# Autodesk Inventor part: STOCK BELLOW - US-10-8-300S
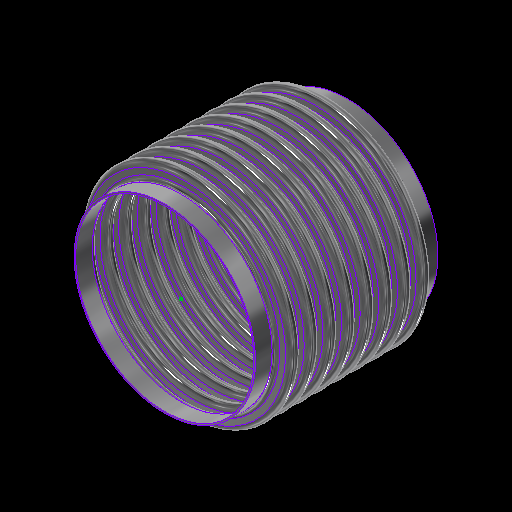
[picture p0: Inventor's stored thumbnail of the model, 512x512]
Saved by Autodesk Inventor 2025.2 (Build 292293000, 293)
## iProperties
Category: 18 GA (0.048 THICK)
RuleStatus: InUse
Created: 2024-01
Part Number: STOCK BELLOW - US-10-8-300S
Project: =STOCK BELLOWS: <Stock Number><SFILL>
Material: ASTM A240-304
Description: =STOCK BELLOWS: <Stock Number>, <SID_> I.D., <SOD_> O.D., <SPLY_> PLY, <Category>, <SNET_CONS> CONS.<PITCH_><STANGENT_> TANGENT<SFILL>
Document SubType Name: Sheet Metal
Designer: GS
Stock Number: U.S-10-8-300S
Surface Area: 10342.1 cm^2
Volume: 1245.47 cm^3
Sheet Metal Rule: Default
Appearance: STAINLESS STEEL
Mass: 10035.1 g
Density: 8.05729 g/cm^3
THK: 0.036
ID: 3.500
OD: 4.250
CONS_: 2
PITCH: 0.500
TANGENT: 0.500
BELLOWS_UPSET: 0.000
d79: 1.000
d82: 1.000
d83: 26.000
d84: 24.000
d174: 8
d214: 8
STHK_: 0.048
SID_: 10.750
SOD_: 12.750
SPITCH_: 1.125
STANGENT__: 1.000
SBELLOWS_UPSET_: 0.000
SDIFF_TAN: 1.000
d252: 2
d275: 2
d287: 0.050
d289: 0.500
d290: 0.000
SOD_NECK: 10 15/16
PLY: 1
PSET: 4.178
PBAR: 1.035
COUNTER: 1.500
NET_TUBE: 3.071
CONS: 2
S_CONS: 0
NET_CONS: 2
ID_M: 88.90 mm
OD_M: 107.95 mm
THK_M: 0.91 mm
ID_U: 3.500 in
OD_U: 4.250 in
THK_U: 0.036 in
TANGENT2: 0.500
TAN_TO_TAN: 1.000 in
d80: 2.571
d81: 10
SID: 2.375
SCONS_: 8
SPITCH: 0.250
STANGENT_: 1.000
SBELLOWS_UPSET: 0.000
SNET_CONS: 8
SS_CONS: 0
SCONS: 8
d190: 8
d191: 1
d192: 1
d193: 8
d194: 0
SIZE: 10.00
PRESSURE: 300
d230: 8
STANGENT: 4.000
SPLY_: 2
d233: 8
d234: 0
d263: 2
d265: 1
d268: 2
d269: 0
d286: 2
d288: 1
d291: 2
d292: 0
SREROLL: 0.750
BLETP: 0.000 ul
PRES_Copy: 85
MATTABLE: 20 GA (0.036 THICK)
PART_NUMBER: U.S-10-8-300S
PITCH_: =, <SPITCH_> PITCH,
CFILL: .
SFILL: .
MESH: ,
COMP: 1.52
EXT: 0.76
LAT: 0.38
ANG: 573
ASR: 6274
LSR: 20302
ANSR: 1890
PRES: 300
COMPM: 15.2
EXTM: 7.6
LATM: 3.80
ASRM: 1098.766
PRESM: 20.684
LSRM: 3555.489
ANSRM: 330.996
TEMPMIN: 20
TEMPMAX: 800
TEMPMINM: -7
TEMPMAXM: 427
WEIGHTM: 10.035
WEIGHT: 22.124
Author: GS
Keywords: 20 GA (0.036 THICK)
Comments: =STOCK BELLOW - <STOCK NUMBER>
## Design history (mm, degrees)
sketch "Sketch2"
  geometry: L1 (0, -177.245)-(0, 562.856) reference; L2 (45.364, 0)-(44.45, 0); L3 (48.082, -2.718)-(50.343, -2.718); L4 (48.082, -3.632)-(50.343, -3.632); L5 (50.343, -9.982)-(48.082, -9.982); L6 (50.343, -9.068)-(48.082, -9.068); L7 (45.364, -12.7)-(44.45, -12.7); L8 (48.082, 0)-(48.082, -12.7); L9 (50.343, -6.35)-(53.975, -6.35); L10 (44.45, 0)-(44.45, -12.7); L11 (20.376, 102.841)-(20.376, 101.926); L12 (58.262, 457.127)-(58.262, 349.177); L13 (58.262, 444.427)-(58.262, 336.477); L14 (93.133, -58.817)-(93.133, -71.517); L15 (118.746, -66.401)-(118.746, -66.401); L16 (50.343, -9.068)-(50.343, -9.982); L17 (48.082, -9.068)-(48.082, -9.982); L18 (48.082, -9.525)-(50.343, -9.525); L19 (53.975, 0)-(53.975, -12.7); L20 (-50.343, -9.068)-(-50.343, -9.982); L21 (-50.343, -2.718)-(-48.082, -2.718); L22 (-50.343, -3.632)-(-48.082, -3.632); L23 (-48.082, -9.068)-(-50.343, -9.068); L24 (-50.343, -9.525)-(-48.082, -9.525); L25 (-48.082, -9.982)-(-50.343, -9.982); L26 (-48.082, -9.068)-(-48.082, -9.982); L27 (-44.45, 0.653)-(-44.45, -12.047); L28 (-48.082, -6.35)-(-44.45, -6.35); L29 (-50.343, 0.653)-(-50.343, -12.7); L30 (-53.061, 0)-(-53.975, 0); L31 (-53.975, 0)-(-53.975, -12.7); L32 (-53.061, -12.7)-(-53.975, -12.7); A1 r 2.718 centre (48.082, 0) between (45.364, 0) and (48.082, -2.718); A2 r 3.632 centre (48.082, 0) between (44.45, 0) and (48.082, -3.632); A3 r 3.632 centre (50.343, -6.35) between (50.343, -9.982) and (50.343, -2.718); A4 r 2.718 centre (50.343, -6.35) between (50.343, -9.068) and (50.343, -3.632); A5 r 2.718 centre (48.082, -12.7) between (48.082, -9.982) and (45.364, -12.7); A6 r 3.632 centre (48.082, -12.7) between (48.082, -9.068) and (44.45, -12.7); A7 r 3.175 centre (50.343, -6.35) between (50.343, -9.525) and (53.518, -6.35); A8 r 3.175 centre (48.082, -12.7) between (48.082, -9.525) and (44.907, -12.7); A9 r 2.718 centre (-50.343, -12.7) between (-50.343, -9.982) and (-53.061, -12.7); A10 r 2.718 centre (-48.082, -6.35) between (-48.082, -9.068) and (-48.082, -3.632); A11 r 3.175 centre (-48.082, -6.35) between (-48.082, -9.525) and (-44.907, -6.35); A12 r 3.632 centre (-48.082, -6.35) between (-48.082, -9.982) and (-48.082, -2.718); A13 r 3.175 centre (-50.343, -12.7) between (-50.343, -9.525) and (-53.518, -12.7); A14 r 3.632 centre (-50.343, -12.7) between (-50.343, -9.068) and (-53.975, -12.7); A15 r 2.718 centre (-50.343, 0) between (-53.061, 0) and (-50.343, -2.718); A16 r 3.632 centre (-50.343, 0) between (-53.975, 0) and (-50.343, -3.632); 10 further points
  constraints: 62 end point, 38 point on circle, 20 tangent, 16 centre point, 12 parallel, 9 midpoint, 7 vertical, 6 coincident, 6 concentric, 6 point on line, 4 equal radius, 4 perpendicular, 3 horizontal, 1 collinear, 1 horizontal alignment, 10 other
  dimensions: "THK" = 0.9144 distance of L11.start L11.end; "ID" = 88.9 distance of L11.end point (20.376, 13.026); "OD" = 107.95 distance of L12.start L12.end; "PITCH" = 12.7 distance of L12.start L13.start; "TANGENT" = 12.7 distance of L14.start L14.end; "BELLOWS_UPSET" = 0 distance of L15.start L15.end; "d43" = 88.9 diameter of L10 L1 (= ID); "d44" = 107.95 diameter of L9.end L1 (= OD); "d45" = 0.9144 distance between parallel lines of L5 L6 (computed from THK, PLY); "d46" = 3.6322 radius of A3 (computed from PITCH, THK, PLY); "UPSET_PITCH" = 12.7 distance of L2.end L7.end (derived); "SIDEWALL_ANGLE" = 360 deg dimension on L3 L9 (derived); "CON_GAP" = 5.4356 distance of point (48.082, -9.068) point (48.082, -3.632) (derived); "TAN1" = 4.98728 dimension on A8 (derived); "TAN2" = 4.98728 dimension on A7 (derived); "LEG1" = 2.2606 distance of L18.start L18.end (derived); "d278" = 0.9144 distance between parallel lines of L25 L23 (derived); "d279" = 3.6322 radius of A12 (derived); "d280" = 12.7 distance of L30.end L31.end (derived); "d281" = 360 deg dimension on L21 L28 (derived); "d282" = 5.4356 distance of point (-50.343, -9.068) point (-50.343, -3.632) (derived); "d283" = 4.98728 dimension on A13 (derived); "d284" = 4.98728 dimension on A11 (derived); "d285" = 2.2606 distance of L24.start L24.end (derived); "d293" = 88.9 diameter of L27 L1 (derived); "d294" = 107.95 diameter of L31 L1 (derived)
  node "Sketch Rectangular Pattern1" dims "d31" = 25.4, "ID" = 88.9
  node "Sketch Rectangular Pattern2" dims "d39" = 25.4, "PITCH" = 12.7
revolve "CONS" stored, may be unused: angle "d48" = 90 deg
node "BELLOW MIDPLANE"
pattern_linear "Rectangular Pattern2" dims "d52" = 12.7 (= UPSET_PITCH)
sketch "Sketch5"
  geometry: C1 r 45.364 at (0, 0) reference; C2 r 44.45 at (0, 0) reference
extrude "TANGENT" new body sketch "Sketch5" distance "d53" = 12.7 (= TANGENT); taper "d54" = 0 deg
revolve "SAMETAN" stored, may be unused: angle "d65" = 90 deg
revolve "DIFFTAN" stored, may be unused: angle "d70" = 90 deg
sketch "Sketch9"
  geometry: L1 (53.319, 0)-(-53.319, 0) reference; L2 (0, -17.78)-(0, 17.78) reference; L3 (38.085, 0)-(-38.085, 0); L4 (38.085, -11.906)-(38.085, 11.906); L5 (25.385, -11.906)-(25.385, 11.906); L6 (13.15, 11.906)-(13.15, -11.906); L7 (-25.385, -11.906)-(-25.385, 11.906); L8 (-38.085, -11.906)-(-38.085, 11.906); L9 (37.291, -11.906)-(37.291, 11.906); L10 (38.085, -11.906)-(37.291, -11.906); L11 (38.085, 11.906)-(37.291, 11.906); L12 (13.546, 11.906)-(12.753, 11.906); L13 (12.753, 11.906)-(12.753, -11.906); L14 (12.753, -11.906)-(13.546, -11.906); L15 (13.546, -11.906)-(13.546, 11.906); L16 (-13.546, 11.906)-(-13.546, -11.906); L17 (-13.15, 11.906)-(-13.15, -11.906); L18 (-13.546, -11.906)-(-12.753, -11.906); L19 (-12.753, -11.906)-(-12.753, 11.906); L20 (-12.753, 11.906)-(-13.546, 11.906); L21 (-38.085, -11.906)-(-37.291, -11.906); L22 (-37.291, -11.906)-(-37.291, 11.906); L23 (-37.291, 11.906)-(-38.085, 11.906); L24 (-38.085, 11.906)-(-38.085, -11.906); L25 (38.085, -0.397)-(-38.085, -0.397); L26 (-38.085, -0.397)-(-38.085, 0.397); L27 (-38.085, 0.397)-(38.085, 0.397); L28 (38.085, 0.397)-(38.085, -0.397); L29 (-38.085, 11.906)-(38.085, 11.906); L30 (38.085, 11.906)-(38.085, 12.7); L31 (38.085, 12.7)-(-38.085, 12.7); L32 (-38.085, 12.7)-(-38.085, 11.906); L33 (38.085, -11.906)-(-38.085, -11.906); L34 (-38.085, -11.906)-(-38.085, -12.7); L35 (-38.085, -12.7)-(38.085, -12.7); L36 (38.085, -12.7)-(38.085, -11.906); 30 further points
  constraints: 68 end point, 13 midpoint, 13 parallel, 8 horizontal, 7 perpendicular, 6 equal length, 3 point on line, 2 vertical, 14 other
  dimensions: "d115" = 23.8125 distance of L4.start L4.end (derived); "d116" = 12.7 distance between parallel lines of L4 L5 (derived); "d117" = 12.23516 distance between parallel lines of L5 L6 (derived); "d125" = 38.53427 distance between parallel lines of L7 L6 (derived); "d127" = 12.7 distance between parallel lines of L8 L7 (derived); "d128" = 24.93516 distance between parallel lines of L6 L4 (derived); "d130" = 76.16943 distance between parallel lines of L8 L4 (derived); "RULER_THK" = 0.79375 distance between parallel lines of L4 L9; "d135" = 0.79375 distance of L13.end L14.end (derived); "d138" = 26.29911 distance of L13.end L16.end (derived); "d143" = 0.79375 distance of L22.end L8.end (derived); "d144" = 0.79375 distance between parallel lines of L27 L25 (derived)
extrude "RULER" join sketch "Sketch9" distance "d149" = 0.79375 (derived); taper "d150" = 0 deg
extrude "BARS" join sketch "Sketch9" distance "d151" = 0.79375 (derived); taper "d152" = 0 deg
pattern_linear "Rectangular Pattern4" dims "d155" = 26.29911 (derived)
sketch "Sketch13"
  geometry: L1 (93.149, -52.467)-(93.149, -77.867); L2 (138.963, 0)-(136.525, 0); L3 (138.963, -28.575)-(136.525, -28.575); L4 (153.562, -22.65)-(144.888, -22.65); L5 (153.562, -20.212)-(144.888, -20.212); L6 (153.562, -14.287)-(161.925, -14.287); L7 (144.888, -5.925)-(153.562, -5.925); L8 (144.888, 0)-(144.888, -28.575); L9 (136.525, 0)-(136.525, -28.575); L10 (58.254, -172.581)-(58.254, -496.431); L11 (58.254, -201.156)-(58.254, -525.006); L12 (58.254, -258.306)-(58.254, -582.156); L13 (58.254, -286.881)-(58.254, -610.731); L14 (58.254, -315.456)-(58.254, -639.306); L15 (58.254, -344.031)-(58.254, -667.881); L16 (58.254, -372.606)-(58.254, -696.456); L17 (58.254, -229.731)-(58.254, -553.581); L18 (20.376, 103.145)-(20.376, 101.926); L19 (144.888, -8.363)-(153.562, -8.363); L20 (0, -856.376)-(0, 263.066) reference; L21 (-32.385, 0)-(194.31, 0) reference; A1 r 5.925 centre (144.888, 0) between (138.963, 0) and (144.888, -5.925); A2 r 5.925 centre (144.888, -28.575) between (144.888, -22.65) and (138.963, -28.575); A3 r 8.363 centre (144.888, -28.575) between (144.888, -20.212) and (136.525, -28.575); A4 r 5.925 centre (153.562, -14.287) between (153.562, -20.212) and (153.562, -8.363); A5 r 8.363 centre (153.562, -14.287) between (153.562, -22.65) and (153.562, -5.925); A6 r 8.363 centre (144.888, 0) between (136.525, 0) and (144.888, -8.363); 6 further points; 1 other entity
  constraints: 38 end point, 15 point on circle, 9 tangent, 6 centre point, 6 parallel, 5 vertical alignment, 4 point on line, 4 vertical, 3 coincident, 3 concentric, 2 collinear, 2 equal radius, 1 horizontal, 1 perpendicular, 23 other
  dimensions: "SBELLOWS_UPSET_" = 0 distance of point (118.762, -66.401) point (118.762, -66.401); "STOTAL_THK_BELLOW__" = 2.4384 distance between parallel lines of L4 L5 (derived); "d224" = 8.36295 radius of A5 (derived); "d225" = 28.575 distance of L2.end L3.end (derived); "SSIDEWALL_ANGLE_" = 360 deg dimension on L7 L6 (derived); "SSCON_GAP_" = 11.8491 distance of point (144.888, -20.212) point (144.888, -8.363) (derived); "d235" = 273.05 diameter of L9 L20 (derived); "d236" = 323.85 diameter of L6.end L20 (derived)
  node "Sketch Rectangular Pattern4" dims "d228" = 25.4
  node "Sketch Rectangular Pattern5" dims "d229" = 25.4
revolve "SBELLOW" stored, may be unused: angle "d197" = 90 deg
pattern_linear "Rectangular Pattern5" dims "d204" = 28.575 (derived)
revolve "STANGENT" stored, may be unused: angle "d240" = 90 deg
revolve "SSAMETAN" stored, may be unused: angle "d241" = 90 deg
revolve "SDIFFTAN" stored, may be unused: angle "d246" = 90 deg
revolve "INVCON" stored, may be unused: angle "d295" = 90 deg
pattern_linear "Rectangular Pattern6" dims "d298" = 12.7 (derived)
revolve "INVTANGENT" stored, may be unused: angle "d302" = 90 deg
revolve "INVSAMETAN" stored, may be unused: angle "d307" = 90 deg
revolve "INVDIFFTAN" stored, may be unused: angle "d312" = 90 deg
sketch "ID BELLOW MOUNT CALC"
  geometry: L1 (44.45, 0)-(38.1, 0); L2 (38.1, 0)-(38.1, 12.7); L3 (38.1, 12.7)-(44.45, 12.7); L4 (44.45, 12.7)-(44.45, 0); L5 (36.513, 12.7)-(35.598, 12.7); L6 (35.598, 12.7)-(35.598, 0); L7 (35.598, 0)-(36.513, 0); L8 (36.513, 0)-(36.513, 12.7); L9 (0, -2.54)-(0, 15.24) reference; L10 (-8.89, 0)-(53.34, 0) reference; 1 further point
  constraints: 16 end point, 5 parallel, 2 collinear, 2 horizontal, 2 perpendicular
  dimensions: "d314" = 12.7 distance of L5.end L6.end (derived); "d315" = 0.9144 distance of L5.start L5.end (derived); "IG" = 1.5875 distance between parallel lines of L2 L8; "PIPE_OD" = 88.9 diameter of L4 L9; "PIPE_WALL" = 6.35 distance of L2.end L3.end; "ID_MT_BELLOW" = 71.1962 diameter of L6 L9 (derived)
revolve "CFILL" stored, may be unused: angle "d320" = 90 deg
pattern_linear "Rectangular Pattern7" dims "d323" = 12.7 (derived)
revolve "SFILL" stored, may be unused: angle "d324" = 90 deg
pattern_linear "Rectangular Pattern8" dims "d327" = 28.575 (derived)
node "STOCK BELLOW MIDPLANE"
node "BELLOW"
sketch "Sketch6"
  geometry: L1 (-12.7, 45.364)-(0, 45.364); L2 (0, 45.364)-(0, 44.45); L3 (0, 44.45)-(-12.7, 44.45); L4 (-12.7, 44.45)-(-12.7, 45.364); L5 (10.16, 0)-(-60.96, 0) reference; L6 (-38.1, -89.422)-(-38.1, 153.44) reference; 1 further point
  constraints: 8 end point, 2 parallel, 1 horizontal, 1 perpendicular
  dimensions: "d61" = 12.7 distance of L2.end L3.end (derived); "d62" = 0.9144 distance of L1.end L2.end (derived); "d63" = 88.9 diameter of L3 L5 (derived); "d64" = 25.4 distance between parallel lines of L4 L6 (derived)
sketch "Sketch12"
  geometry: 1 further point
sketch "Sketch14"
  geometry: L1 (-25.4, 138.963)-(0, 138.963); L2 (0, 138.963)-(0, 136.525); L3 (0, 136.525)-(-25.4, 136.525); L4 (-25.4, 136.525)-(-25.4, 138.963); L5 (5.08, 0)-(-30.48, 0) reference; L6 (0, -27.793)-(0, 166.756) reference; 1 further point
  constraints: 8 end point, 2 parallel, 1 collinear, 1 horizontal, 1 perpendicular
  dimensions: "d237" = 2.4384 distance of L3.end L1.start (derived); "d238" = 273.05 diameter of L3 L5 (derived); "d239" = 25.4 distance of L1.start L1.end (derived); "SOD_NECK" = 277.9268 diameter of L1 L5 (derived)
sketch "Sketch15"
  geometry: L1 (-27.793, 0)-(166.756, 0) reference; L2 (136.525, -228.6)-(138.963, -228.6); L3 (138.963, -228.6)-(138.963, -254); L4 (138.963, -254)-(136.525, -254); L5 (136.525, -254)-(136.525, -228.6); L6 (0, -307.34)-(0, 66.04) reference; 1 further point
  constraints: 8 end point, 2 parallel, 1 horizontal, 1 perpendicular
  dimensions: "d205" = 25.4 distance of L4.end L2.start (derived); "d206" = 2.4384 distance of L3.end L4.end (derived); "d207" = 273.05 diameter of L5 L6 (derived); "d208" = 228.6 distance between parallel lines of L1 L2 (derived)
node "TANGENT_"
node "SAME_TAN"
sketch "Sketch8"
  geometry: L1 (45.364, -25.4)-(44.45, -25.4); L2 (44.45, -25.4)-(44.45, -38.1); L3 (44.45, -38.1)-(45.364, -38.1); L4 (45.364, -38.1)-(45.364, -25.4); L5 (0, -48.26)-(0, 22.86) reference; L6 (-89.422, 0)-(153.44, 0) reference; 1 further point
  constraints: 8 end point, 2 parallel, 1 horizontal, 1 perpendicular
  dimensions: "d66" = 88.9 diameter of L2 L5 (derived); "TOTAL_THK_BELLOW" = 0.9144 distance of L2.end L3.end (derived); "d68" = 25.4 distance between parallel lines of L1 L6 (derived); "d69" = 12.7 distance of L1.end L2.end (derived)
node "DIFF_TAN"
node "Sketch Rectangular Pattern3" dims "d138" = 26.29911 (derived), "d141" = 25.4
node "SBELLOW_"
node "STANGENT_"
node "SSAME_TAN"
sketch "Sketch16"
  geometry: L1 (138.963, -228.6)-(136.525, -228.6); L2 (136.525, -228.6)-(136.525, -254); L3 (136.525, -254)-(138.963, -254); L4 (138.963, -254)-(138.963, -228.6); L5 (0, -307.34)-(0, 66.04) reference; L6 (-27.793, 0)-(166.756, 0) reference; 1 further point
  constraints: 8 end point, 2 parallel, 1 horizontal, 1 perpendicular
  dimensions: "SDIFF_TAN" = 25.4 distance of L3.end L1.start; "d243" = 2.4384 distance of L2.end L3.end (derived); "d244" = 228.6 distance between parallel lines of L1 L6 (derived); "d245" = 273.05 diameter of L2 L5 (derived)
node "SDIFF_TAN"
body "Solid15"
sketch "Sketch17"
  geometry: L1 (53.975, 12.7)-(53.061, 12.7); L2 (53.061, 12.7)-(53.061, 0); L3 (53.061, 0)-(53.975, 0); L4 (53.975, 0)-(53.975, 12.7); L5 (0, -2.54)-(0, 15.24) reference; L6 (-10.795, 0)-(64.77, 0) reference; 2 further points
  constraints: 8 end point, 2 parallel, 1 horizontal, 1 midpoint, 1 perpendicular, 1 point on line
  dimensions: "INVTANGENT" = 12.7 distance of L3.end L1.start (derived); "d300" = 0.9144 distance of L1.start L1.end (derived); "d301" = 107.95 diameter of L4 L5 (derived)
body "Solid16"
sketch "Sketch18"
  geometry: L1 (53.975, -25.4)-(53.061, -25.4); L2 (53.061, -25.4)-(53.061, -38.1); L3 (53.061, -38.1)-(53.975, -38.1); L4 (53.975, -38.1)-(53.975, -25.4); L5 (-10.795, 0)-(64.77, 0) reference; L6 (0, -48.26)-(0, 22.86) reference; 1 further point
  constraints: 8 end point, 2 parallel, 1 horizontal, 1 perpendicular
  dimensions: "d303" = 25.4 distance between parallel lines of L1 L5 (derived); "d304" = 12.7 distance of L3.end L1.start (derived); "d305" = 0.9144 distance of L2.end L3.end (derived); "d306" = 107.95 diameter of L4 L6 (derived)
body "Solid17"
sketch "Sketch19"
  geometry: L1 (53.975, -25.4)-(53.061, -25.4); L2 (53.061, -25.4)-(53.061, -38.1); L3 (53.061, -38.1)-(53.975, -38.1); L4 (53.975, -38.1)-(53.975, -25.4); L5 (0, -48.26)-(0, 22.86) reference; L6 (-10.795, 0)-(64.77, 0) reference; 1 further point
  constraints: 8 end point, 2 parallel, 1 horizontal, 1 perpendicular
  dimensions: "d308" = 12.7 distance of L1.end L2.end (derived); "d309" = 107.95 diameter of L4 L5 (derived); "d310" = 0.9144 distance of L2.end L3.end (derived); "d311" = 25.4 distance between parallel lines of L1 L6 (derived)
body "Solid18"
body "Solid19"
body "Solid20"
other parameters: "BMPL" = -114.3, "PSET" = 106.1212 (computed from OD, THK, PLY) [user parameter], "PBAR" = 26.29911 (= 0.570796 x PITCH + OD - ID) [user parameter; used in 1 equation term], "COUNTER" = 15 [user parameter], "NET_TUBE" = 77.99823 (computed from CONS_, PBAR, TANGENT) [user parameter], "S_CONS" = 0 [user parameter; used in 1 equation term], "ID_M" = 88.9 (= ID) [user parameter], "OD_M" = 107.95 (= OD) [user parameter], "THK_M" = 0.9144 (= THK) [user parameter], "ID_U" = 88.9 (= ID) [user parameter], "OD_U" = 107.95 (= OD) [user parameter], "THK_U" = 0.9144 (= THK) [user parameter], "D_UNITS" = 0 [user parameter], "TANGENT2" = 12.7 [user parameter], "TAN_TO_TAN" = 25.4 [user parameter], "OD_NECK" = 90.7288 [user parameter], "d79" = 25.4, "d80" = 65.29823 [user parameter], "d82" = 25.4, "d83" = 660.4, "d84" = 609.6, "sa_0" = 4, "FRAME_THK" = 0.79375 [user parameter], "CON_FLAT" = 12.23516 [user parameter], "SID" = 60.325 [user parameter], "SPITCH" = 6.35 [user parameter], "STANGENT_" = 25.4 [user parameter], "SBELLOWS_UPSET" = 0 [user parameter], "SS_CONS" = 0 [user parameter], "STAN_TO_TAN_" = 228.6 [user parameter], "d100" = 2.4384 [user parameter], "d191" = 25.4 [user parameter], "d194" = 0 [user parameter], "STANGENT" = 101.6 [user parameter], "d234" = 0 [user parameter], "SUPSET_PITCH_" = 28.575 [user parameter], "d269" = 0 [user parameter], "d287" = 1.27, "d289" = 12.7, "d290" = 0, "d292" = 0 [user parameter], "Thickness" = 3.048 (derived), "KFactor" = 4.4, "BendRadius" = 3.048 (derived), "BendReliefWidth" = 3.048 (derived), "BendReliefDepth" = 1.524 (derived), "CornerReliefSize" = 12.192 (derived), "SeamGap" = 0.00508, "MinimumRemnant" = 6.096 (derived), "TransitionRadius" = 3.048 (derived), "JacobiRadiusSize" = 3.048 (derived), "GapSize" = 3.048 (derived), "SREROLL" = 19.05 [user parameter], "CUR_STK_PITCH" = 28.575 [user parameter], "d328" = -114.3 (derived), "ASR" = 62740 [user parameter], "LSR" = 203020 [user parameter], "ANSR" = 18900 [user parameter], "BLETP" = 0 [user parameter], "ASRM" = 10987.6562 [user parameter], "PRESM" = 206.83949 [user parameter], "LSRM" = 35554.8926 [user parameter], "ANSRM" = 3309.957 [user parameter], "TEMPMIN" = 2664.83333 [user parameter], "TEMPMAX" = 6998.16667 [user parameter], "TEMPMINM" = 2664.83333 [user parameter], "TEMPMAXM" = 6998.16667 [user parameter], "WEIGHT" = 100.35095 [user parameter], "WEIGHTM" = 0.10035 [user parameter]
